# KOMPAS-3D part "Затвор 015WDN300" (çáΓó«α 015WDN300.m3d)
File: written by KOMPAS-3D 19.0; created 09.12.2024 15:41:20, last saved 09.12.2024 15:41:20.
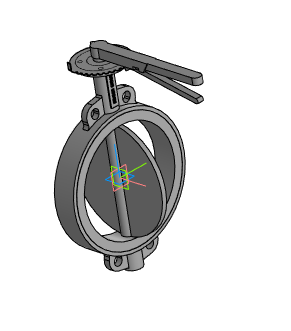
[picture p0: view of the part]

Document properties: Автор: Евгений; Полное имя файла: ..\Затвор 015WDN300.a3d

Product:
- Part/product: Затвор 015WDN300
    Масса: 37.0783

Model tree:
1. Операция без истории:1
